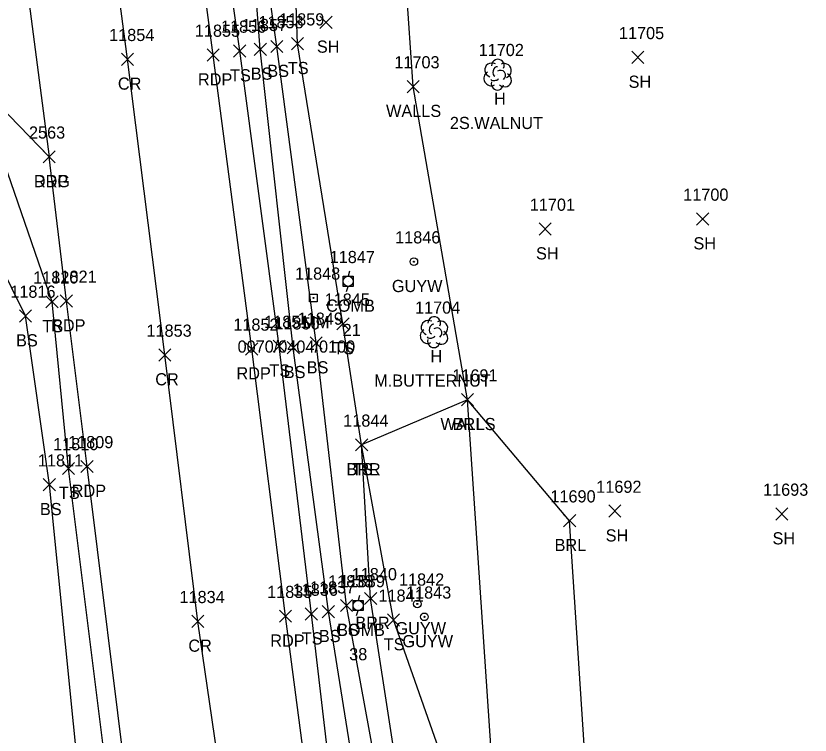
# Model space of a CAD drawing. Extents: x 1439173 to 1457902, y 641926 to 659889.
# Drawn here: x 1447903.7 to 1448034.3, y 648625.8 to 648744.1 of the extents above; entities that cross this region are included whole.
import ezdxf

# ---------------------------------------------------------------- set-up
doc = ezdxf.new("R2010")
doc.units = 0
for name, color, linetype in [('L_A', 7, 'Continuous'), ('L_C', 7, 'Continuous'), ('L_I', 7, 'Continuous'), ('L_TIC', 7, 'Continuous'), ('LABL', 7, 'Continuous'), ('LELB', 7, 'Continuous'), ('LTD', 7, 'Continuous'), ('LWS', 7, 'Continuous'), ('P_A', 7, 'Continuous'), ('P_I', 7, 'Continuous'), ('P_TIC', 7, 'Continuous'), ('PET', 7, 'Continuous'), ('PRC', 7, 'Continuous'), ('R_A', 7, 'Continuous'), ('R_I', 7, 'Continuous'), ('R_TIC', 7, 'Continuous'), ('RDG', 7, 'Continuous'), ('S_A', 7, 'Continuous'), ('S_C', 7, 'Continuous'), ('S_I', 7, 'Continuous'), ('SRM', 7, 'Continuous'), ('U_A', 7, 'Continuous'), ('U_C', 7, 'Continuous'), ('U_I', 7, 'Continuous'), ('UP', 7, 'Continuous'), ('UPGW', 7, 'Continuous')]:
    doc.layers.add(name, color=color, linetype=linetype)

msp = doc.modelspace()

# ---------------------------------------------------------------- linework, layer by layer
at = {"layer": 'L_TIC'}
for points in [[(1447953.7, 648742.01), (1447955.7, 648744.01)], [(1447955.7, 648742.01), (1447953.7, 648744.01)], [(1447945.6, 648738.03), (1447947.6, 648740.03)], [(1447947.6, 648738.03), (1447945.6, 648740.03)], [(1447949, 648738.49), (1447951, 648740.49)], [(1447951, 648738.49), (1447949, 648740.49)], [(1447939.5, 648737.3), (1447941.5, 648739.3)], [(1447941.5, 648737.3), (1447939.5, 648739.3)], [(1447942.88, 648737.57), (1447944.88, 648739.57)], [(1447944.88, 648737.57), (1447942.88, 648739.57)], [(1448004.94, 648736.24), (1448006.94, 648738.24)], [(1448006.94, 648736.24), (1448004.94, 648738.24)], [(1447968.02, 648731.44), (1447970.02, 648733.44)], [(1447970.02, 648731.44), (1447968.02, 648733.44)], [(1448015.6, 648709.67), (1448017.6, 648711.67)], [(1448017.6, 648709.67), (1448015.6, 648711.67)], [(1447989.72, 648708.02), (1447991.72, 648710.02)], [(1447991.72, 648708.02), (1447989.72, 648710.02)], [(1447908.66, 648696.05), (1447910.66, 648698.05)], [(1447910.66, 648696.05), (1447908.66, 648698.05)], [(1447904.3, 648693.72), (1447906.3, 648695.72)], [(1447906.3, 648693.72), (1447904.3, 648695.72)], [(1447956.48, 648692.42), (1447958.48, 648694.42)], [(1447958.48, 648692.42), (1447956.48, 648694.42)], [(1447956.48, 648692.42), (1447958.48, 648694.42)], [(1447958.48, 648692.42), (1447956.48, 648694.42)], [(1447945.98, 648688.75), (1447947.98, 648690.75)], [(1447947.98, 648688.75), (1447945.98, 648690.75)], [(1447948.31, 648688.51), (1447950.31, 648690.51)], [(1447950.31, 648688.51), (1447948.31, 648690.51)], [(1447952.07, 648689.28), (1447954.07, 648691.28)], [(1447954.07, 648689.28), (1447952.07, 648691.28)], [(1447976.96, 648679.95), (1447978.96, 648681.95)], [(1447978.96, 648679.95), (1447976.96, 648681.95)], [(1447976.96, 648679.95), (1447978.96, 648681.95)], [(1447978.96, 648679.95), (1447976.96, 648681.95)], [(1447959.54, 648672.52), (1447961.54, 648674.52)], [(1447961.54, 648672.52), (1447959.54, 648674.52)], [(1447959.54, 648672.52), (1447961.54, 648674.52)], [(1447961.54, 648672.52), (1447959.54, 648674.52)], [(1447959.54, 648672.52), (1447961.54, 648674.52)], [(1447961.54, 648672.52), (1447959.54, 648674.52)], [(1447911.37, 648668.65), (1447913.37, 648670.65)], [(1447913.37, 648668.65), (1447911.37, 648670.65)], [(1447908.22, 648665.97), (1447910.22, 648667.97)], [(1447910.22, 648665.97), (1447908.22, 648667.97)], [(1448001.18, 648661.64), (1448003.18, 648663.64)], [(1448003.18, 648661.64), (1448001.18, 648663.64)], [(1448028.61, 648661.16), (1448030.61, 648663.16)], [(1448030.61, 648661.16), (1448028.61, 648663.16)], [(1447993.73, 648660.06), (1447995.73, 648662.06)], [(1447995.73, 648660.06), (1447993.73, 648662.06)], [(1447961.02, 648647.27), (1447963.02, 648649.27)], [(1447963.02, 648647.27), (1447961.02, 648649.27)], [(1447957.07, 648646.1), (1447959.07, 648648.1)], [(1447959.07, 648646.1), (1447957.07, 648648.1)], [(1447951.29, 648644.71), (1447953.29, 648646.71)], [(1447953.29, 648644.71), (1447951.29, 648646.71)], [(1447954.08, 648645.1), (1447956.08, 648647.1)], [(1447956.08, 648645.1), (1447954.08, 648647.1)], [(1447964.77, 648643.74), (1447966.77, 648645.74)], [(1447966.77, 648643.74), (1447964.77, 648645.74)]]:
    msp.add_lwpolyline(points, dxfattribs=at)
at = {"layer": 'LABL'}
for points in [[(1447979.13, 648514.69), (1447981.23, 648503.4), (1447992.5, 648494.26), (1448009.81, 648487.44), (1448045.94, 648493), (1448048.9, 648506.29), (1448012.47, 648506.76), (1448011.17, 648524.23), (1448005.77, 648573.48), (1447997.97, 648611.66), (1447994.73, 648661.06), (1447977.96, 648680.95), (1447960.54, 648673.52)], [(1447979.13, 648514.69), (1447977.26, 648546.38), (1447969.8, 648597.73), (1447962.02, 648648.27), (1447960.54, 648673.52)]]:
    msp.add_lwpolyline(points, dxfattribs=at)
at = {"layer": 'LELB'}
for points in [[(1447974.79, 648514.27), (1447972.12, 648545.7), (1447967.29, 648596.82), (1447958.07, 648647.1), (1447953.07, 648690.28), (1447946.6, 648739.03), (1447940.66, 648780.96), (1447936.37, 648827.1), (1447928.59, 648872.23), (1447920.72, 648916.47), (1447916.19, 648958.02), (1447909.98, 648994.25), (1447909.19, 648998.29), (1447909.54, 649003.59), (1447916.36, 649010.63), (1447924.3, 649013.7), (1447944.43, 649018.61)], [(1447969.85, 648514.47), (1447964.49, 648544.65), (1447957.95, 648597.38), (1447952.29, 648645.71), (1447946.98, 648689.75), (1447940.5, 648738.3), (1447934.59, 648780.28), (1447929.04, 648824.88), (1447922.4, 648871.3), (1447916.32, 648916.62), (1447909.85, 648957.42), (1447904.84, 648993.23), (1447904.91, 648998.9), (1447906.94, 649001.32), (1447909.54, 649003.59), (1447912.95, 649002.53)], [(1447957.48, 648693.42), (1447950, 648739.49), (1447949.69, 648749.17), (1447943.12, 648781.41), (1447938.92, 648828.83), (1447932.09, 648872.31), (1447927.36, 648915.79), (1447920.66, 648958.97), (1447913.2, 648994.89), (1447912.95, 649002.53)], [(1447971.97, 648514.34), (1447968.59, 648545.51), (1447962.76, 648598.05), (1447955.08, 648646.1), (1447949.31, 648689.51), (1447943.88, 648738.57), (1447940.65, 648781.02), (1447931.82, 648826.68), (1447925.82, 648871.76), (1447918.72, 648916.18), (1447912.39, 648957.17), (1447907.99, 648993.99), (1447906.16, 648998.51), (1447906.81, 648999.55), (1447907.58, 648999.87), (1447909.19, 648998.29)], [(1447909.66, 648697.05), (1447900.62, 648723.15)], [(1447857.92, 648532.04), (1447874.33, 648528.1), (1447893.57, 648529.78), (1447914.68, 648536.88), (1447921.41, 648543.42), (1447921.85, 648560.74), (1447920.34, 648585.99), (1447914.48, 648614.57), (1447909.22, 648666.97), (1447905.3, 648694.72), (1447898.39, 648708.6)], [(1447874.33, 648528.1), (1447895.68, 648524.62), (1447912.89, 648527.69), (1447920.24, 648531.8), (1447926.49, 648541.09), (1447925.57, 648561.75), (1447922.67, 648586.46), (1447919.13, 648615.29), (1447912.37, 648669.65), (1447909.66, 648697.05)], [(1447985.24, 648516.19), (1447988.97, 648543.38), (1447984.33, 648572), (1447977.11, 648612.47), (1447965.77, 648644.74), (1447960.54, 648673.52), (1447957.48, 648693.42)]]:
    msp.add_lwpolyline(points, dxfattribs=at)
at = {"layer": 'LTD'}
for p, q in [((1447982.88, 648734.46), (1447982.88, 648734.46)), ((1447982.88, 648734.46), (1447982.88, 648734.46)), ((1447972.42, 648692.1), (1447972.42, 648692.1)), ((1447972.42, 648692.1), (1447972.42, 648692.1))]:
    msp.add_line(p, q, dxfattribs=at)
for centre in [(1447982.93, 648735.89), (1447972.47, 648693.53)]:
    msp.add_arc(centre, 1.05, 335.5272, 180.9563, dxfattribs=at)
for centre, major_axis, ratio, start_param, end_param in [((1447982.09, 648735.12), (1.21, -0.51), 0.895232, 1.570796, 4.712389), ((1447983.92, 648735.04), (-1.14, -0.48), 0.949671, 1.570796, 4.712389), ((1447981.8, 648733.75), (0.58, -1.04), 0.959034, 3.141593, 6.283185), ((1447982.67, 648734.92), (-0.208, -0.792), 0.645439, 3.141593, 6.283185), ((1447983.38, 648734.29), (-0.5, 0.667), 0.989748, 3.141593, 6.283185), ((1447982.42, 648733.71), (-0.625, -0.083), 0.423636, 0, 3.141593), ((1447983.88, 648733.62), (-1.09, 0.79), 0.841452, 1.570796, 4.712389), ((1447982.88, 648732.96), (0.26, 1.06), 0.942809, 1.570796, 4.712389), ((1447971.63, 648692.77), (1.21, -0.51), 0.895232, 1.570796, 4.712389), ((1447972.22, 648692.56), (-0.208, -0.792), 0.645439, 3.141593, 6.283185), ((1447973.47, 648692.68), (-1.14, -0.48), 0.949671, 1.570796, 4.712389), ((1447971.34, 648691.39), (0.58, -1.04), 0.959034, 3.141593, 6.283185), ((1447972.92, 648691.93), (-0.5, 0.667), 0.989748, 3.141593, 6.283185), ((1447973.42, 648691.27), (-1.09, 0.79), 0.841452, 1.570796, 4.712389), ((1447972.42, 648690.6), (0.26, 1.06), 0.942809, 1.570796, 4.712389), ((1447971.97, 648691.35), (-0.625, -0.083), 0.423636, 0, 3.141593)]:
    msp.add_ellipse(centre, major_axis=major_axis, ratio=ratio, start_param=start_param, end_param=end_param, dxfattribs=at)
at = {"layer": 'LWS'}
msp.add_lwpolyline([(1447995.63, 648530.22), (1447987.41, 648570.8), (1447982.71, 648610.28), (1447977.96, 648680.95), (1447969.02, 648732.44), (1447965.97, 648777.26), (1447965.56, 648784.62), (1447961.57, 648816.89), (1447953.14, 648865.36), (1447946.25, 648895.81)], dxfattribs=at)
at = {"layer": 'P_TIC'}
for points in [[(1447921.05, 648735.93), (1447923.05, 648737.93)], [(1447923.05, 648735.93), (1447921.05, 648737.93)], [(1447935.15, 648736.63), (1447937.15, 648738.63)], [(1447937.15, 648736.63), (1447935.15, 648738.63)], [(1447908.17, 648719.89), (1447910.17, 648721.89)], [(1447910.17, 648719.89), (1447908.17, 648721.89)], [(1447911.01, 648696.18), (1447913.01, 648698.18)], [(1447913.01, 648696.18), (1447911.01, 648698.18)], [(1447927.19, 648687.31), (1447929.19, 648689.31)], [(1447929.19, 648687.31), (1447927.19, 648689.31)], [(1447941.48, 648688.3), (1447943.48, 648690.3)], [(1447943.48, 648688.3), (1447941.48, 648690.3)], [(1447914.4, 648668.98), (1447916.4, 648670.98)], [(1447916.4, 648668.98), (1447914.4, 648670.98)], [(1447947.04, 648644.35), (1447949.04, 648646.35)], [(1447949.04, 648644.35), (1447947.04, 648646.35)], [(1447932.63, 648643.51), (1447934.63, 648645.51)], [(1447934.63, 648643.51), (1447932.63, 648645.51)]]:
    msp.add_lwpolyline(points, dxfattribs=at)
at = {"layer": 'PET'}
for points in [[(1447985.99, 648352.77), (1447984.12, 648388.61), (1447978.58, 648406.37), (1447976.75, 648417.49), (1447970.56, 648463.48), (1447964.44, 648514.86), (1447960.48, 648544.49), (1447954.4, 648596.97), (1447948.04, 648645.35), (1447942.48, 648689.3), (1447936.15, 648737.63), (1447930.52, 648780.21), (1447924.61, 648825.68), (1447919.43, 648871), (1447912.62, 648916.56), (1447907.24, 648956.8), (1447902.54, 648992.52), (1447895.42, 649044.11)], [(1447912.01, 648697.18), (1447909.17, 648720.89)], [(1447925.25, 648591.92), (1447922.16, 648615.83), (1447915.4, 648669.98), (1447912.01, 648697.18)]]:
    msp.add_lwpolyline(points, dxfattribs=at)
at = {"layer": 'PRC'}
msp.add_lwpolyline([(1448032.33, 647961.7), (1448025.03, 648003.46), (1448015.67, 648063.56), (1448008.21, 648110.03), (1448001.08, 648156.37), (1447993.04, 648207.4), (1447985.4, 648256.52), (1447977.63, 648310.23), (1447970.83, 648357.73), (1447966.46, 648396.63), (1447963.75, 648410.58), (1447956.84, 648463.17), (1447947.44, 648542.38), (1447940.67, 648596), (1447933.63, 648644.51), (1447928.19, 648688.31), (1447922.05, 648736.93), (1447916.64, 648778.15)], dxfattribs=at)
at = {"layer": 'R_TIC'}
for points in [[(1447908.17, 648719.89), (1447910.17, 648721.89)], [(1447910.17, 648719.89), (1447908.17, 648721.89)]]:
    msp.add_lwpolyline(points, dxfattribs=at)
at = {"layer": 'RDG'}
for points in [[(1447899.12, 648797.86), (1447909.17, 648720.89)], [(1447802.51, 648730.75), (1447851.24, 648736.8), (1447877.88, 648738.45), (1447894.33, 648736.16), (1447909.17, 648720.89)]]:
    msp.add_lwpolyline(points, dxfattribs=at)
at = {"layer": 'SRM'}
msp.add_lwpolyline([(1447951.99, 648698.32), (1447953.24, 648698.32), (1447953.24, 648697.07), (1447951.99, 648697.07)], close=True, dxfattribs=at)
msp.add_circle((1447952.62, 648697.69), 0.0833, dxfattribs=at)
at = {"layer": 'UP'}
for p, q in [((1447958.57, 648702.09), (1447958.32, 648701.25)), ((1447957.49, 648699.59), (1447957.49, 648701.25)), ((1447957.49, 648701.25), (1447959.15, 648701.25)), ((1447959.15, 648701.25), (1447959.15, 648699.59)), ((1447959.15, 648699.59), (1447957.49, 648699.59)), ((1447958.07, 648698.75), (1447958.32, 648699.59)), ((1447958.32, 648700.42), (1447958.32, 648700.42)), ((1447960.21, 648648.78), (1447959.96, 648647.95)), ((1447959.13, 648646.28), (1447959.13, 648647.95)), ((1447959.13, 648647.95), (1447960.8, 648647.95)), ((1447960.8, 648647.95), (1447960.8, 648646.28)), ((1447960.8, 648646.28), (1447959.13, 648646.28)), ((1447959.71, 648645.45), (1447959.96, 648646.28)), ((1447959.96, 648647.11), (1447959.96, 648647.11))]:
    msp.add_line(p, q, dxfattribs=at)
for centre in [(1447958.32, 648700.42), (1447959.96, 648647.11)]:
    msp.add_circle(centre, 0.833, dxfattribs=at)
at = {"layer": 'UPGW'}
for centre, radius in [((1447969.13, 648703.65), 0.625), ((1447969.13, 648703.65), 0.0833), ((1447969.7, 648647.38), 0.625), ((1447969.7, 648647.38), 0.0833), ((1447970.86, 648645.25), 0.625), ((1447970.86, 648645.25), 0.0833)]:
    msp.add_circle(centre, radius, dxfattribs=at)

# ---------------------------------------------------------------- texts
at = {"layer": 'L_A'}
for s, p in [('SH', (1447953.19, 648738.01)), ('BS', (1447945.04, 648734.03)), ('TS', (1447948.41, 648734.49)), ('TS', (1447938.91, 648733.3)), ('BS', (1447942.32, 648733.57)), ('SH', (1448004.43, 648732.24)), ('H', (1447982.31, 648729.46)), ('WALLS', (1447964.56, 648727.44)), ('SH', (1448015.09, 648705.67)), ('SH', (1447989.21, 648704.02)), ('TS', (1447908.07, 648692.05)), ('BS', (1447903.74, 648689.72)), ('TS', (1447955.89, 648688.42)), ('TS', (1447955.89, 648688.42)), ('H', (1447971.86, 648687.1)), ('TS', (1447945.39, 648684.75)), ('BS', (1447947.75, 648684.51)), ('BS', (1447951.51, 648685.28)), ('WALLS', (1447973.5, 648675.95)), ('BRL', (1447975.5, 648675.95)), ('BRR', (1447958.03, 648668.52)), ('BRL', (1447958.08, 648668.52)), ('TS', (1447958.95, 648668.52)), ('TS', (1447910.78, 648664.65)), ('BS', (1447907.66, 648661.97)), ('SH', (1448000.66, 648657.64)), ('SH', (1448028.09, 648657.16)), ('BRL', (1447992.27, 648656.06)), ('BRR', (1447959.51, 648643.27)), ('BS', (1447956.52, 648642.1)), ('TS', (1447950.7, 648640.71)), ('BS', (1447953.52, 648641.1)), ('TS', (1447964.18, 648639.74))]:
    msp.add_text(s, height=2, dxfattribs=at).set_placement(p)
at = {"layer": 'L_C'}
for s, p in [('2S.WALNUT', (1447975.05, 648725.46)), ('M.BUTTERNUT', (1447962.61, 648683.1))]:
    msp.add_text(s, height=2, dxfattribs=at).set_placement(p)
at = {"layer": 'L_I'}
for s, p in [('11858', (1447943.57, 648742.03)), ('11859', (1447946.97, 648742.49)), ('11856', (1447937.42, 648741.3)), ('11857', (1447940.85, 648741.57)), ('11705', (1448002.84, 648740.24)), ('11702', (1447979.78, 648737.46)), ('11703', (1447965.92, 648735.44)), ('11700', (1448013.41, 648713.67)), ('11701', (1447988.18, 648712.02)), ('11820', (1447906.55, 648700.05)), ('11816', (1447902.79, 648697.72)), ('11845', (1447954.46, 648696.42)), ('11845', (1447954.46, 648696.42)), ('11704', (1447969.32, 648695.1)), ('11851', (1447944.52, 648692.75)), ('11850', (1447946.2, 648692.51)), ('11849', (1447950.03, 648693.28)), ('11691', (1447975.45, 648683.95)), ('11691', (1447975.45, 648683.95)), ('11844', (1447957.52, 648676.52)), ('11844', (1447957.52, 648676.52)), ('11844', (1447957.52, 648676.52)), ('11810', (1447909.83, 648672.65)), ('11811', (1447907.33, 648669.97)), ('11692', (1447999.11, 648665.64)), ('11693', (1448026.53, 648665.16)), ('11690', (1447991.57, 648664.06)), ('11840', (1447958.91, 648651.27)), ('11838', (1447955.05, 648650.1)), ('11836', (1447949.21, 648648.71)), ('11837', (1447952.05, 648649.1)), ('11841', (1447963.31, 648647.74))]:
    msp.add_text(s, height=2, dxfattribs=at).set_placement(p)
at = {"layer": 'P_A'}
for s, p in [('CR', (1447920.48, 648731.93)), ('RDP', (1447933.64, 648732.63)), ('RDP', (1447906.66, 648715.89)), ('RDP', (1447909.5, 648692.18)), ('CR', (1447926.62, 648683.31)), ('RDP', (1447939.97, 648684.3)), ('RDP', (1447912.89, 648664.98)), ('RDP', (1447945.53, 648640.35)), ('CR', (1447932.06, 648639.51))]:
    msp.add_text(s, height=2, dxfattribs=at).set_placement(p)
at = {"layer": 'P_I'}
for s, p in [('11855', (1447933.13, 648740.63)), ('11854', (1447919.03, 648739.93)), ('2563', (1447905.86, 648723.89)), ('11821', (1447909.55, 648700.18)), ('11852', (1447939.45, 648692.3)), ('11853', (1447925.17, 648691.31)), ('11809', (1447912.29, 648672.98)), ('11835', (1447945.01, 648648.35)), ('11834', (1447930.6, 648647.51))]:
    msp.add_text(s, height=2, dxfattribs=at).set_placement(p)
at = {"layer": 'R_A'}
msp.add_text('DRG', height=2, dxfattribs=at).set_placement((1447906.66, 648715.89))
at = {"layer": 'R_I'}
msp.add_text('2563', height=2, dxfattribs=at).set_placement((1447905.86, 648723.89))
at = {"layer": 'S_A'}
msp.add_text('MM', height=2, dxfattribs=at).set_placement((1447950.81, 648692.69))
at = {"layer": 'S_C'}
msp.add_text('0070/0404/0100', height=2, dxfattribs=at).set_placement((1447940.15, 648688.69))
at = {"layer": 'S_I'}
msp.add_text('11848', height=2, dxfattribs=at).set_placement((1447949.59, 648700.69))
at = {"layer": 'U_A'}
for s, p in [('GUYW', (1447965.52, 648698.65)), ('COMB', (1447954.7, 648695.42)), ('COMB', (1447956.35, 648642.11)), ('GUYW', (1447966.1, 648642.38)), ('GUYW', (1447967.25, 648640.25))]:
    msp.add_text(s, height=2, dxfattribs=at).set_placement(p)
at = {"layer": 'U_C'}
for s, p in [('21', (1447957.42, 648691.42)), ('38', (1447958.5, 648638.11))]:
    msp.add_text(s, height=2, dxfattribs=at).set_placement(p)
at = {"layer": 'U_I'}
for s, p in [('11846', (1447966.05, 648706.65)), ('11847', (1447955.29, 648703.42)), ('11839', (1447956.93, 648650.11)), ('11842', (1447966.68, 648650.38)), ('11843', (1447967.84, 648648.25))]:
    msp.add_text(s, height=2, dxfattribs=at).set_placement(p)

doc.saveas('drawing.dxf')
